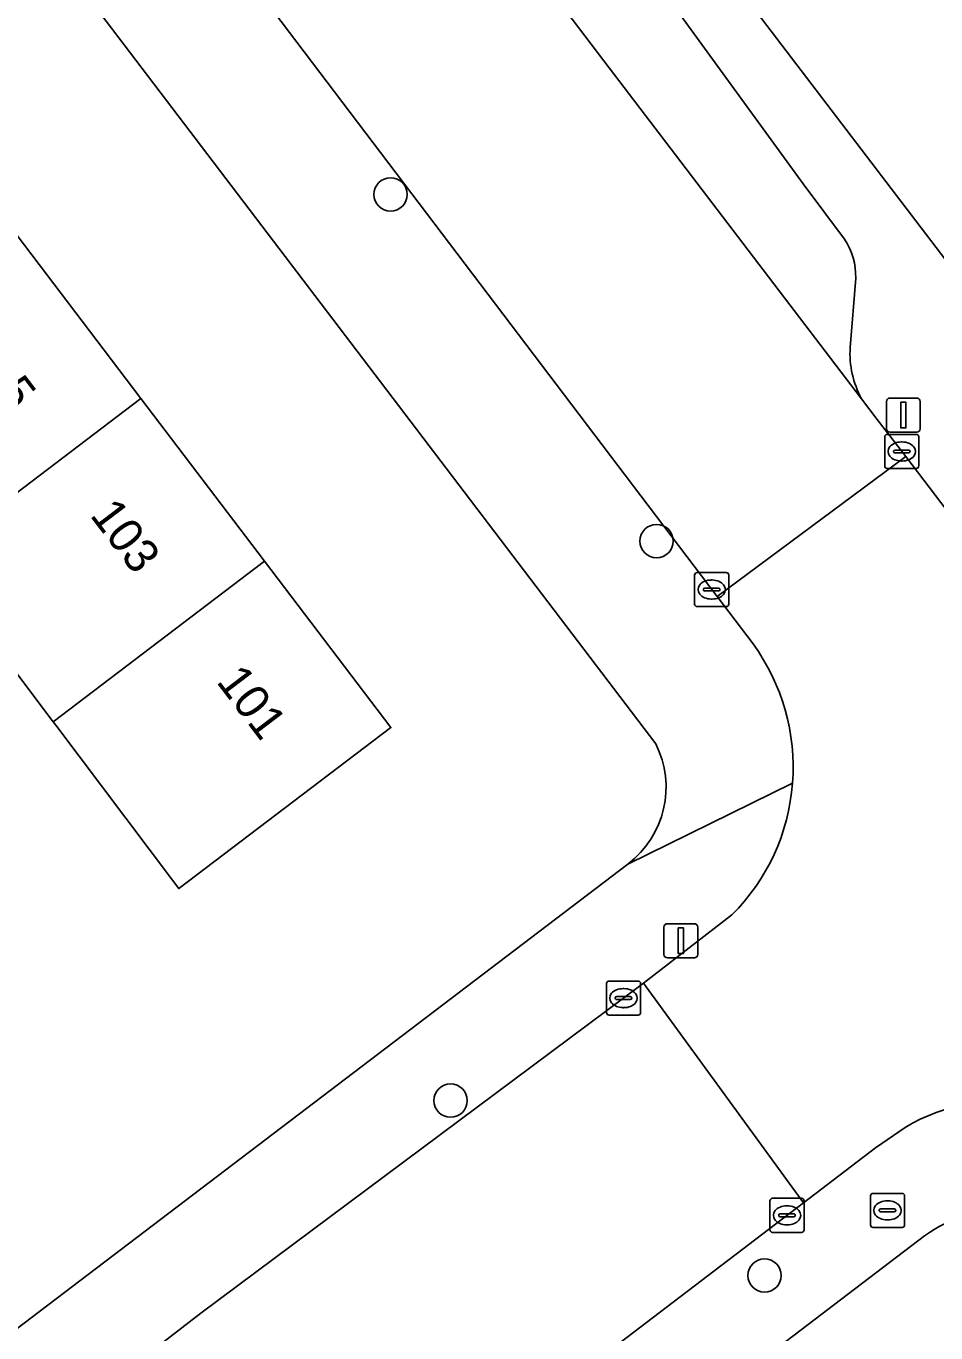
# Model space of a CAD drawing. Extents: x 160030 to 160839, y 385325 to 386450.
# Drawn here: x 160407.21 to 160433.9, y 385780.35 to 385818.69 of the extents above; entities that cross this region are included whole.
import ezdxf

# ---------------------------------------------------------------- set-up
doc = ezdxf.new("R2010")
doc.units = 0
for name, color, linetype in [('IMGEO_Boom', 7, 'Continuous'), ('IMGEO_Brandkraan', 7, 'Continuous'), ('IMGEO_Erf', 7, 'Continuous'), ('IMGEO_Kolk', 7, 'Continuous'), ('IMGEO_Lichtmast', 7, 'Continuous'), ('IMGEO_Pand', 7, 'Continuous'), ('IMGEO_Pand_nummerreeks', 7, 'Continuous'), ('IMGEO_Parkeervlak_open', 7, 'Continuous'), ('IMGEO_Rijbaan_lokaal_gesloten', 7, 'Continuous'), ('IMGEO_Rijbaan_lokaal_open', 7, 'Continuous'), ('IMGEO_Voetpad_open', 7, 'Continuous')]:
    doc.layers.add(name, color=color, linetype=linetype)

msp = doc.modelspace()

# ---------------------------------------------------------------- linework, layer by layer
at = {"layer": 'IMGEO_Boom'}
for centre in [(160417.905, 385813.755), (160425.708, 385803.583), (160419.666, 385787.169), (160428.877, 385782.038)]:
    msp.add_circle(centre, 0.489, dxfattribs=at)
at = {"layer": 'IMGEO_Brandkraan'}
for p, q in [((160431.983, 385783.521), (160431.983, 385784.373)), ((160432.058, 385784.447), (160432.91, 385784.447)), ((160432.984, 385784.373), (160432.984, 385783.521)), ((160432.285, 385783.99), (160432.683, 385783.99)), ((160432.471, 385784.227), (160432.496, 385784.227)), ((160432.242, 385783.941), (160432.242, 385783.953)), ((160432.68, 385783.904), (160432.282, 385783.904)), ((160432.494, 385783.667), (160432.469, 385783.667)), ((160432.726, 385783.953), (160432.726, 385783.941)), ((160432.91, 385783.447), (160432.058, 385783.447))]:
    msp.add_line(p, q, dxfattribs=at)
for points in [[(160431.983, 385783.521), (160431.983, 385784.373)], [(160432.058, 385784.447), (160432.91, 385784.447)], [(160432.984, 385784.373), (160432.984, 385783.521)], [(160432.91, 385783.447), (160432.058, 385783.447)]]:
    msp.add_lwpolyline(points, dxfattribs=at)
for centre, radius, start, end in [((160432.06, 385784.371), 0.0765, 91.552, 178.448), ((160432.06, 385784.371), 0.0765, 91.552, 178.448), ((160432.908, 385784.371), 0.0765, 1.552, 88.448), ((160432.908, 385784.371), 0.0765, 1.552, 88.448), ((160432.282, 385783.95), 0.0403, 85.8775, 175.7526), ((160432.687, 385783.952), 0.0386, 1.7309, 96.639), ((160432.279, 385783.94), 0.0366, 178.938, 274.7102), ((160432.683, 385783.947), 0.043, 264.8664, 352.4533), ((160432.06, 385783.523), 0.0765, 181.552, 268.448), ((160432.06, 385783.523), 0.0765, 181.552, 268.448), ((160432.908, 385783.523), 0.0765, 271.552, 358.448), ((160432.908, 385783.523), 0.0765, 271.552, 358.448)]:
    msp.add_arc(centre, radius, start, end, dxfattribs=at)
for centre, major_axis, ratio, start_param, end_param in [((160432.47, 385783.947), (-0.387, 0.002), 0.722429, 4.712389, 7.853982), ((160432.495, 385783.947), (-0.39, 0.002), 0.717154, 1.570796, 4.712389)]:
    msp.add_ellipse(centre, major_axis=major_axis, ratio=ratio, start_param=start_param, end_param=end_param, dxfattribs=at)
at = {"layer": 'IMGEO_Erf'}
for points in [[(160425.684, 385797.636), (160365.182, 385877.181)], [(160467.463, 385842.567), (160469.844, 385844.381), (160463.561, 385852.624), (160458.547, 385848.802), (160460.94, 385845.697), (160458.995, 385844.199), (160456.333, 385842.148), (160453.941, 385845.253), (160448.054, 385840.924), (160450.43, 385837.841), (160448.874, 385836.653), (160446.135, 385834.562), (160443.773, 385837.627), (160438.306, 385833.163), (160440.377, 385830.449), (160438.706, 385829.174), (160433.311, 385825.057), (160431.24, 385827.77), (160425.422, 385823.334), (160437.717, 385807.206)], [(160399.687, 385822.098), (160403.316, 385817.321), (160406.947, 385812.544), (160410.577, 385807.767), (160414.206, 385802.99), (160417.912, 385798.113), (160411.69, 385793.391), (160411.509, 385793.632), (160408.079, 385798.185), (160408.008, 385798.279), (160404.399, 385803.072), (160400.79, 385807.864), (160397.18, 385812.658), (160393.57, 385817.45), (160389.96, 385822.243)], [(160379.773, 385820.336), (160382.575, 385816.635), (160385.586, 385812.658), (160383.578, 385811.138), (160385.012, 385809.268), (160387.001, 385810.774), (160389.812, 385807.062), (160392.815, 385803.096), (160390.826, 385801.59), (160392.329, 385799.662), (160394.322, 385801.189), (160397.118, 385797.54), (160400.181, 385793.542), (160398.188, 385792.015), (160399.617, 385790.332), (160401.599, 385791.824), (160404.494, 385787.977), (160402.512, 385786.485), (160406.915, 385780.456), (160424.865, 385794.109)], [(160433.573, 385783.199), (160389.993, 385750)]]:
    msp.add_lwpolyline(points, dxfattribs=at)
for centre, radius, start, end in [((160423.155, 385796.365), 2.831, 307.1716, 26.6826), ((160435.648, 385780.463), 3.434, 81.858, 127.1706)]:
    msp.add_arc(centre, radius, start, end, dxfattribs=at)
at = {"layer": 'IMGEO_Kolk'}
for p, q in [((160432.402, 385805.786), (160432.402, 385806.638)), ((160432.477, 385806.712), (160433.329, 385806.712)), ((160433.403, 385806.638), (160433.403, 385805.786)), ((160432.661, 385806.206), (160432.661, 385806.218)), ((160432.704, 385806.255), (160433.102, 385806.255)), ((160432.89, 385806.492), (160432.915, 385806.492)), ((160433.145, 385806.218), (160433.145, 385806.206)), ((160433.099, 385806.169), (160432.701, 385806.169)), ((160432.913, 385805.932), (160432.888, 385805.932)), ((160433.329, 385805.712), (160432.477, 385805.712)), ((160426.825, 385801.736), (160426.825, 385802.588)), ((160426.9, 385802.662), (160427.752, 385802.662)), ((160427.313, 385802.442), (160427.338, 385802.442)), ((160427.826, 385802.588), (160427.826, 385801.736)), ((160427.084, 385802.156), (160427.084, 385802.168)), ((160427.522, 385802.119), (160427.124, 385802.119)), ((160427.127, 385802.205), (160427.525, 385802.205)), ((160427.568, 385802.168), (160427.568, 385802.156)), ((160427.752, 385801.662), (160426.9, 385801.662)), ((160427.336, 385801.882), (160427.311, 385801.882)), ((160424.238, 385789.749), (160424.238, 385790.601)), ((160424.313, 385790.675), (160425.165, 385790.675)), ((160425.239, 385790.601), (160425.239, 385789.749)), ((160424.497, 385790.169), (160424.497, 385790.181)), ((160424.935, 385790.132), (160424.537, 385790.132)), ((160424.54, 385790.218), (160424.938, 385790.218)), ((160424.726, 385790.455), (160424.751, 385790.455)), ((160424.981, 385790.181), (160424.981, 385790.169)), ((160424.749, 385789.895), (160424.724, 385789.895)), ((160425.165, 385789.675), (160424.313, 385789.675)), ((160429.035, 385783.377), (160429.035, 385784.229)), ((160429.11, 385784.303), (160429.962, 385784.303)), ((160429.523, 385784.083), (160429.548, 385784.083)), ((160430.036, 385784.229), (160430.036, 385783.377)), ((160429.294, 385783.797), (160429.294, 385783.809)), ((160429.732, 385783.76), (160429.334, 385783.76)), ((160429.337, 385783.846), (160429.735, 385783.846)), ((160429.778, 385783.809), (160429.778, 385783.797)), ((160429.962, 385783.303), (160429.11, 385783.303)), ((160429.546, 385783.523), (160429.521, 385783.523))]:
    msp.add_line(p, q, dxfattribs=at)
for points in [[(160432.402, 385805.786), (160432.402, 385806.638)], [(160432.477, 385806.712), (160433.329, 385806.712)], [(160433.403, 385806.638), (160433.403, 385805.786)], [(160433.329, 385805.712), (160432.477, 385805.712)], [(160426.825, 385801.736), (160426.825, 385802.588)], [(160426.9, 385802.662), (160427.752, 385802.662)], [(160427.826, 385802.588), (160427.826, 385801.736)], [(160427.752, 385801.662), (160426.9, 385801.662)], [(160424.238, 385789.749), (160424.238, 385790.601)], [(160424.313, 385790.675), (160425.165, 385790.675)], [(160425.239, 385790.601), (160425.239, 385789.749)], [(160425.165, 385789.675), (160424.313, 385789.675)], [(160429.035, 385783.377), (160429.035, 385784.229)], [(160429.11, 385784.303), (160429.962, 385784.303)], [(160430.036, 385784.229), (160430.036, 385783.377)], [(160429.962, 385783.303), (160429.11, 385783.303)]]:
    msp.add_lwpolyline(points, dxfattribs=at)
for centre, radius, start, end in [((160432.479, 385806.636), 0.0765, 91.552, 178.448), ((160432.479, 385806.636), 0.0765, 91.552, 178.448), ((160433.327, 385806.636), 0.0765, 1.552, 88.448), ((160433.327, 385806.636), 0.0765, 1.552, 88.448), ((160432.701, 385806.215), 0.0403, 85.8775, 175.7526), ((160432.698, 385806.205), 0.0366, 178.938, 274.7102), ((160433.102, 385806.212), 0.043, 264.8664, 352.4533), ((160433.106, 385806.217), 0.0386, 1.7309, 96.639), ((160432.479, 385805.788), 0.0765, 181.552, 268.448), ((160432.479, 385805.788), 0.0765, 181.552, 268.448), ((160433.327, 385805.788), 0.0765, 271.552, 358.448), ((160433.327, 385805.788), 0.0765, 271.552, 358.448), ((160426.902, 385802.586), 0.0765, 91.552, 178.448), ((160426.902, 385802.586), 0.0765, 91.552, 178.448), ((160427.75, 385802.586), 0.0765, 1.552, 88.448), ((160427.75, 385802.586), 0.0765, 1.552, 88.448), ((160427.124, 385802.165), 0.0403, 85.8775, 175.7526), ((160427.121, 385802.155), 0.0366, 178.938, 274.7102), ((160427.525, 385802.162), 0.043, 264.8664, 352.4533), ((160427.529, 385802.167), 0.0386, 1.7309, 96.639), ((160426.902, 385801.738), 0.0765, 181.552, 268.448), ((160426.902, 385801.738), 0.0765, 181.552, 268.448), ((160427.75, 385801.738), 0.0765, 271.552, 358.448), ((160427.75, 385801.738), 0.0765, 271.552, 358.448), ((160424.315, 385790.599), 0.0765, 91.552, 178.448), ((160424.315, 385790.599), 0.0765, 91.552, 178.448), ((160425.163, 385790.599), 0.0765, 1.552, 88.448), ((160425.163, 385790.599), 0.0765, 1.552, 88.448), ((160424.537, 385790.178), 0.0403, 85.8775, 175.7526), ((160424.534, 385790.168), 0.0366, 178.938, 274.7102), ((160424.938, 385790.175), 0.043, 264.8664, 352.4533), ((160424.942, 385790.18), 0.0386, 1.7309, 96.639), ((160424.315, 385789.751), 0.0765, 181.552, 268.448), ((160424.315, 385789.751), 0.0765, 181.552, 268.448), ((160425.163, 385789.751), 0.0765, 271.552, 358.448), ((160425.163, 385789.751), 0.0765, 271.552, 358.448), ((160429.112, 385784.227), 0.0765, 91.552, 178.448), ((160429.112, 385784.227), 0.0765, 91.552, 178.448), ((160429.96, 385784.227), 0.0765, 1.552, 88.448), ((160429.96, 385784.227), 0.0765, 1.552, 88.448), ((160429.334, 385783.806), 0.0403, 85.8775, 175.7526), ((160429.331, 385783.796), 0.0366, 178.938, 274.7102), ((160429.735, 385783.803), 0.043, 264.8664, 352.4533), ((160429.739, 385783.808), 0.0386, 1.7309, 96.639), ((160429.112, 385783.379), 0.0765, 181.552, 268.448), ((160429.112, 385783.379), 0.0765, 181.552, 268.448), ((160429.96, 385783.379), 0.0765, 271.552, 358.448), ((160429.96, 385783.379), 0.0765, 271.552, 358.448)]:
    msp.add_arc(centre, radius, start, end, dxfattribs=at)
for centre, major_axis, ratio, start_param, end_param in [((160432.889, 385806.212), (-0.387, 0.002), 0.722429, 4.712389, 7.853982), ((160432.914, 385806.212), (-0.39, 0.002), 0.717154, 1.570796, 4.712389), ((160427.312, 385802.162), (-0.387, 0.002), 0.722429, 4.712389, 7.853982), ((160427.337, 385802.162), (-0.39, 0.002), 0.717154, 1.570796, 4.712389), ((160424.725, 385790.175), (-0.387, 0.002), 0.722429, 4.712389, 7.853982), ((160424.75, 385790.175), (-0.39, 0.002), 0.717154, 1.570796, 4.712389), ((160429.522, 385783.803), (-0.387, 0.002), 0.722429, 4.712389, 7.853982), ((160429.547, 385783.803), (-0.39, 0.002), 0.717154, 1.570796, 4.712389)]:
    msp.add_ellipse(centre, major_axis=major_axis, ratio=ratio, start_param=start_param, end_param=end_param, dxfattribs=at)
at = {"layer": 'IMGEO_Lichtmast'}
for p, q in [((160432.552, 385807.78), (160433.342, 385807.78)), ((160433.342, 385807.78), (160432.552, 385807.78)), ((160432.452, 385806.88), (160432.452, 385807.68)), ((160432.452, 385807.68), (160432.452, 385806.88)), ((160433.442, 385807.68), (160433.442, 385806.88)), ((160433.442, 385806.88), (160433.442, 385807.68)), ((160433.342, 385806.78), (160432.552, 385806.78)), ((160432.552, 385806.78), (160433.342, 385806.78)), ((160425.926, 385791.459), (160425.926, 385792.259)), ((160425.926, 385792.259), (160425.926, 385791.459)), ((160426.026, 385792.359), (160426.816, 385792.359)), ((160426.816, 385792.359), (160426.026, 385792.359)), ((160426.916, 385792.259), (160426.916, 385791.459)), ((160426.916, 385791.459), (160426.916, 385792.259)), ((160426.816, 385791.359), (160426.026, 385791.359)), ((160426.026, 385791.359), (160426.816, 385791.359))]:
    msp.add_line(p, q, dxfattribs=at)
for points in [[(160432.872, 385807.655), (160433.022, 385807.655), (160433.022, 385806.905), (160432.872, 385806.905), (160432.872, 385807.655)], [(160426.346, 385792.234), (160426.496, 385792.234), (160426.496, 385791.484), (160426.346, 385791.484), (160426.346, 385792.234)]]:
    msp.add_lwpolyline(points, dxfattribs=at)
for centre, start, end in [((160432.552, 385807.68), 90, 180), ((160432.552, 385807.68), 90, 180), ((160433.342, 385807.68), 0, 90), ((160433.342, 385807.68), 360, 90), ((160432.552, 385806.88), 180, 270), ((160432.552, 385806.88), 180, 270), ((160433.342, 385806.88), 270, 0), ((160433.342, 385806.88), 270, 0), ((160426.026, 385792.259), 90, 180), ((160426.026, 385792.259), 90, 180), ((160426.816, 385792.259), 0, 90), ((160426.816, 385792.259), 360, 90), ((160426.026, 385791.459), 180, 270), ((160426.026, 385791.459), 180, 270), ((160426.816, 385791.459), 270, 0), ((160426.816, 385791.459), 270, 0)]:
    msp.add_arc(centre, 0.1, start, end, dxfattribs=at)
at = {"layer": 'IMGEO_Pand'}
for points in [[(160410.577, 385807.767), (160406.947, 385812.544), (160400.79, 385807.864), (160404.399, 385803.072)], [(160414.206, 385802.99), (160410.577, 385807.767), (160404.399, 385803.072), (160408.008, 385798.279)], [(160411.509, 385793.632), (160411.69, 385793.391), (160417.912, 385798.113), (160414.206, 385802.99), (160408.008, 385798.279), (160408.079, 385798.185)]]:
    msp.add_lwpolyline(points, close=True, dxfattribs=at)
at = {"layer": 'IMGEO_Parkeervlak_open'}
for points in [[(160408.384, 385838.431), (160424.163, 385817.668), (160431.721, 385807.759)], [(160431.226, 385812.44), (160430.01, 385814.065), (160426.251, 385819.223), (160423.934, 385822.272), (160422.974, 385823.535), (160418.888, 385828.913)], [(160431.387, 385809.26), (160431.55, 385811.299)]]:
    msp.add_lwpolyline(points, dxfattribs=at)
for centre, radius, start, end in [((160429.579, 385811.356), 1.972, 358.3467, 33.3583), ((160434.158, 385809.089), 2.776, 176.4649, 208.6251)]:
    msp.add_arc(centre, radius, start, end, dxfattribs=at)
at = {"layer": 'IMGEO_Rijbaan_lokaal_gesloten'}
msp.add_lwpolyline([(160337.484, 385713.901), (160342.671, 385717.746), (160354.26, 385726.531), (160358.201, 385729.526), (160385.133, 385750), (160400.437, 385761.634), (160420.803, 385777.146), (160430.014, 385784.168), (160425.32, 385790.614), (160412.341, 385780.93), (160408.525, 385777.99), (160403.685, 385774.26), (160399.366, 385770.932), (160380.496, 385756.509), (160371.922, 385750), (160352.828, 385735.505), (160337.658, 385723.913), (160332.826, 385720.277)], dxfattribs=at)
at = {"layer": 'IMGEO_Rijbaan_lokaal_open'}
for points in [[(160332.303, 385927.233), (160345.107, 385910.299), (160358.716, 385892.358), (160358.891, 385892.166), (160368.75, 385879.341), (160369.011, 385878.899), (160390.932, 385850.046), (160400.824, 385837.058), (160410.888, 385823.854), (160427.481, 385801.96), (160433.017, 385806.06), (160432.182, 385807.154), (160431.721, 385807.759), (160424.163, 385817.668), (160408.384, 385838.431), (160407.664, 385839.378)], [(160434.231, 385804.47), (160433.017, 385806.06), (160427.481, 385801.96), (160428.538, 385800.565)], [(160427.919, 385792.615), (160425.32, 385790.614), (160430.014, 385784.168), (160432.128, 385785.779), (160432.998, 385786.381)]]:
    msp.add_lwpolyline(points, dxfattribs=at)
for centre, radius, start, end in [((160423.581, 385796.951), 6.135, 355.638, 36.0969), ((160423.583, 385796.952), 6.133, 314.993, 355.6203), ((160435.762, 385781.798), 5.352, 77.9963, 121.096)]:
    msp.add_arc(centre, radius, start, end, dxfattribs=at)
at = {"layer": 'IMGEO_Voetpad_open'}
for points in [[(160363.009, 385881.394), (160365.182, 385877.181), (160425.684, 385797.636)], [(160428.538, 385800.565), (160427.481, 385801.96), (160410.888, 385823.854), (160400.824, 385837.058), (160390.932, 385850.046), (160369.011, 385878.899)], [(160413.171, 385836.435), (160418.888, 385828.913), (160419.285, 385829.216), (160423.371, 385823.838), (160422.974, 385823.535), (160423.934, 385822.272), (160424.331, 385822.575), (160426.648, 385819.526), (160426.251, 385819.223), (160430.01, 385814.065), (160431.226, 385812.44)], [(160437.717, 385807.206), (160425.422, 385823.334)], [(160431.55, 385811.299), (160431.387, 385809.26)], [(160431.721, 385807.759), (160432.182, 385807.154), (160433.017, 385806.06), (160434.231, 385804.47), (160439.559, 385806.143)], [(160429.698, 385796.484), (160424.865, 385794.109), (160406.915, 385780.456), (160401.383, 385776.193), (160366.865, 385750), (160331.329, 385723.034)], [(160424.865, 385794.109), (160429.698, 385796.484)], [(160399.366, 385770.932), (160403.685, 385774.26), (160403.38, 385774.656), (160408.22, 385778.386), (160408.525, 385777.99), (160412.341, 385780.93), (160425.32, 385790.614), (160427.919, 385792.615)], [(160432.998, 385786.381), (160432.128, 385785.779), (160430.014, 385784.168), (160420.803, 385777.146), (160400.437, 385761.634), (160385.133, 385750), (160358.201, 385729.526), (160358.503, 385729.128), (160354.562, 385726.133), (160354.26, 385726.531), (160342.671, 385717.746), (160337.484, 385713.901), (160339.266, 385710.826)], [(160339.818, 385711.772), (160357.171, 385724.957), (160359.486, 385726.76), (160389.993, 385750), (160433.573, 385783.199)]]:
    msp.add_lwpolyline(points, dxfattribs=at)
for centre, radius, start, end in [((160429.579, 385811.356), 1.972, 358.3467, 33.3583), ((160434.158, 385809.089), 2.776, 176.4649, 208.6251), ((160423.581, 385796.951), 6.135, 355.638, 36.0969), ((160423.155, 385796.365), 2.831, 307.1716, 26.6826), ((160423.583, 385796.952), 6.133, 314.993, 355.6203), ((160435.762, 385781.798), 5.352, 77.9963, 121.096), ((160435.648, 385780.463), 3.434, 81.858, 127.1706)]:
    msp.add_arc(centre, radius, start, end, dxfattribs=at)

# ---------------------------------------------------------------- texts
at = {"layer": 'IMGEO_Pand_nummerreeks'}
for s, p in [('105', (160405.422, 385809.128)), ('103', (160409.062, 385804.338)), ('101', (160412.77, 385799.458))]:
    msp.add_text(s, height=1, rotation=307.2297, dxfattribs=at).set_placement(p)

doc.saveas('drawing.dxf')
